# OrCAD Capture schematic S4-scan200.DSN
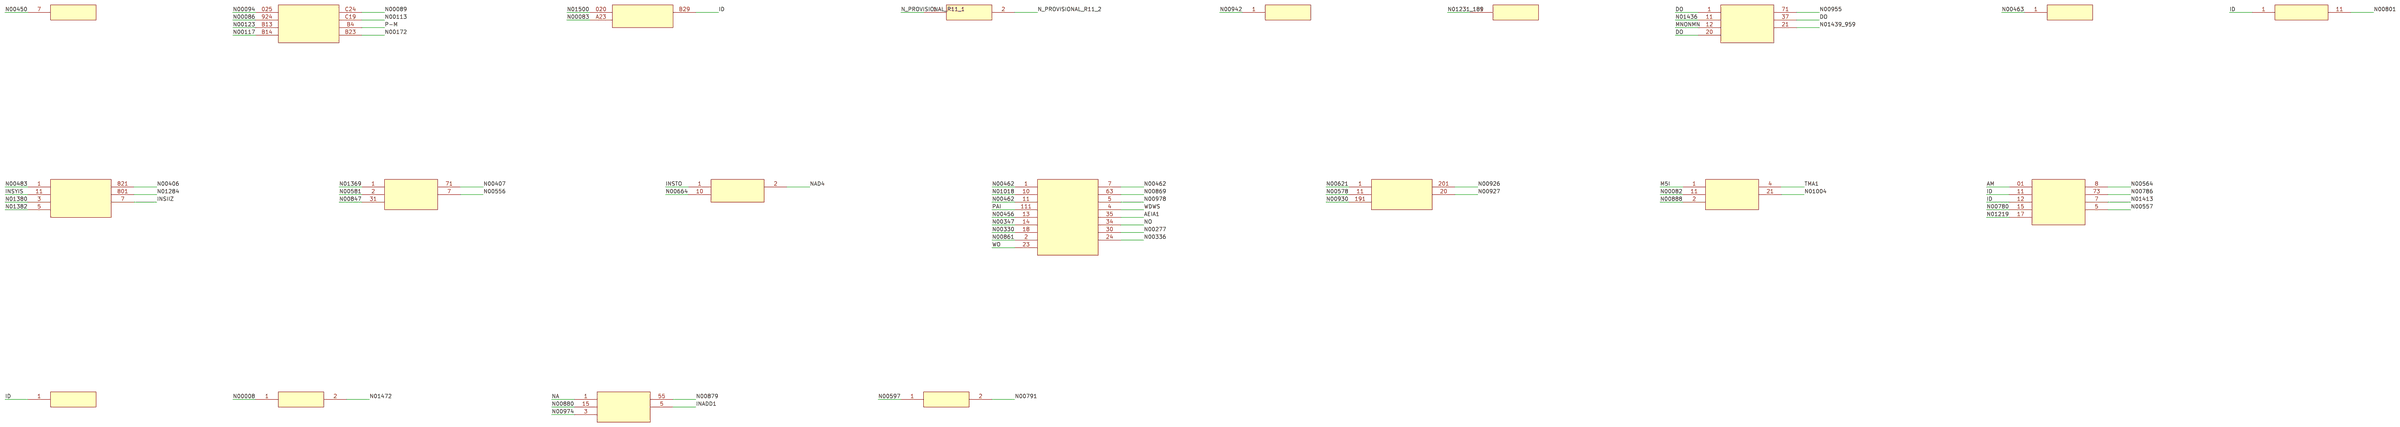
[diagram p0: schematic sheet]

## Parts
J1  CONNECTOR
P1  CONNECTOR
P2  CONNECTOR
R11  1K00
R14  1K00
R20  510R
U16  74F174
U19  74F02
U25  74F240
U27  74F174
U28  74F174
U29  74F174
U31  AM291C
U33  74F240
U34  74F240
U38  74F151
U39  74F00
U40  74F10
U_1  74F240
U_2  74F240

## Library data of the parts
J1 = OBS_J1
P1 = OBS_P1
P2 = OBS_P2
R11 = OBS_R11
R14 = OBS_R14
R20 = OBS_R20
U16 = OBS_U16
U19 = OBS_U19
U25 = OBS_U25
U27 = OBS_U27
U28 = OBS_U28
U29 = OBS_U29
U31 = OBS_U31
U33 = OBS_U33
U34 = OBS_U34
U38 = OBS_U38
U39 = OBS_U39
U40 = OBS_U40
U_1 = OBS_U_1
U_2 = OBS_U_2

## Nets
AEIA1: U31.35
AM: U38.01
DO: U16.1 U16.20 U16.37
ID: P2.B29 U25.1 U38.11 U38.12 U39.1
INADD1: U_1.5
INSIIZ: U27.7
INSTO: U29.1
INSYIS: U27.11
M5I: U34.1
MNONMN: U16.12
N01231_189: R20.1
N01439_959: U16.21
N_PROVISIONAL_R11_1: R11.1
N_PROVISIONAL_R11_2: R11.2
NA: U_1.1
NAD4: U29.2
NO: U31.34
P-M: P1.B4
PAI: U31.111
TMA1: U34.4
WDWS: U31.4
WO: U31.23
N00462: U31.1 U31.7 U31.11

Not connected (* = marked no-connect by the designer): J1 7; P1 025 924 B13 B14 B23 C19 C24; P2 020 A23; R14 1; U16 11 71; U19 1; U25 11; U27 1 3 5 801 821; U28 1 2 7 31 71; U29 10; U31 2 5 10 13 14 18 24 30 63; U33 1 11 20 191 201; U34 2 11 21; U38 5 7 8 15 17 73; U40 1 2; U_1 3 15 55; U_2 1 2
